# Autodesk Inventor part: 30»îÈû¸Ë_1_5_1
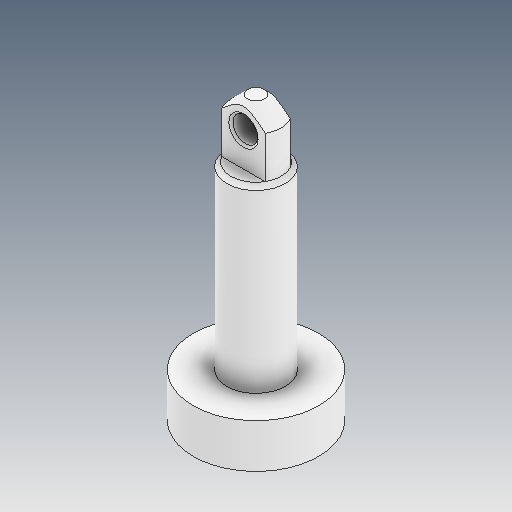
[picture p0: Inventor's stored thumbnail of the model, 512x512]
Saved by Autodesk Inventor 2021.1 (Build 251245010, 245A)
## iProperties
Created: 2021-05
Part Number: 30»îÈû¸Ë_1_5_1
Material: Ogólny
Document SubType Name: Modeling
Designer: user
Density: 1 g/cm^3
Appearance: Domyślna
Author: user
Revision Number: ÈÎºÎ
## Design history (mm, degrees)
feature "ÊäÈë1"
node "Bryła1"
